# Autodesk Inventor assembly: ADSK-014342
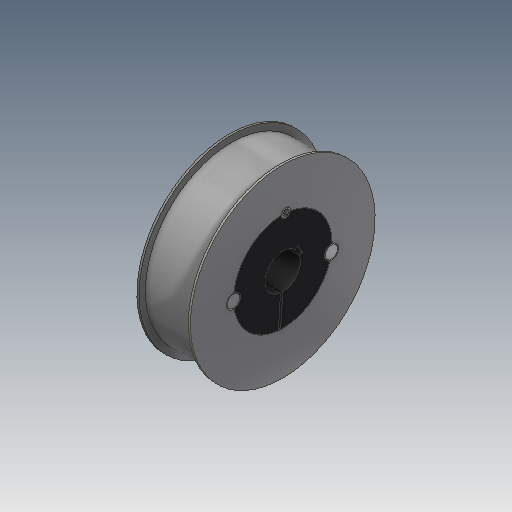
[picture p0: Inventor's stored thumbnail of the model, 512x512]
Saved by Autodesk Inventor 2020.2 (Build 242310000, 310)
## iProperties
Created: 2019-10
Part Number: ADSK-014342
Document SubType Name: Assembly
Designer: lutzd
Mass: 1112.35 g
Surface Area: 666.429 cm^2
Volume: 411.34 cm^3
Density: 2.70421 g/cm^3
VLDS_Profile: Default Assembly
VLDS_TimeStamp: 2016-07-29
VLDS_FailCnt: 0
VLDS_AcceptCnt: 0
Dimensions: 179,9x179,9x38 mm
Mass: 1,112 kg
DocNumber: ADSK-014342
Folder: 01 - Themengebiete\Simplification\01 - Packaging machine\
VDS_Category: 3D Komponenten
VDS_NumSchm: Autodesk
Title: wheel
Author: lutzd
Revision Number: -
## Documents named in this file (5)
- D:\07 - DEMODATEN\OTX 2019 - Dataset - UPDATE - Dez2019\Designs\07-Packing machine\ADSK-014342.iam
- D:\07 - DEMODATEN\OTX 2019 - Dataset - UPDATE - Dez2019\Designs\07-Packing machine\Parts\ADSK-011719.ipt
- D:\07 - DEMODATEN\OTX 2019 - Dataset - UPDATE - Dez2019\Designs\07-Packing machine\Parts\ADSK-011776.ipt
- D:\07 - DEMODATEN\OTX 2019 - Dataset - UPDATE - Dez2019\Content Center Files\de-DE\ISO 8734(2)\ISO 8734 - 10 x 30 - AISO (2).ipt
- D:\07 - DEMODATEN\OTX 2019 - Dataset - UPDATE - Dez2019\Content Center Files\de-DE\ISO 4026\ISO 4026 - M8 x 25 - ISO.ipt
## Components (5 placed, 4 different names)
1. ADSK-011719:1 — Passend:5
2. ADSK-011776:1 — Passend:5, Fluchtend:3
3. ISO 8734 10 x 30 - A:1
4. ISO 8734 10 x 30 - A:2
5. ISO 4026 M8 x 25:1 — Fluchtend:3
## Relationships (2: Mate 1, Flush 1)
- Passend:5 [Mate]: ADSK-011719:1 ↔ ADSK-011776:1
- Fluchtend:3 [Flush]: ADSK-011776:1 ↔ ISO 4026 M8 x 25:1
